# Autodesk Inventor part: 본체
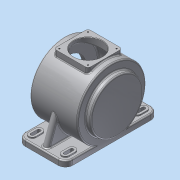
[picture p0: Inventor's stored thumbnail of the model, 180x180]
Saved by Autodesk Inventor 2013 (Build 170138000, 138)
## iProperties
Created: 2015-06
Part Number: 본체
Material: 알루미늄 6061
Document SubType Name: Modeling
Designer: Administrator
Density: 2.71 g/cm^3
Mass: 3326.36 g
Surface Area: 2312.89 cm^2
Volume: 1227.44 cm^3
Author: Administrator
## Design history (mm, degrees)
sketch "스케치1"
  geometry: L1 (-59, 115)-(59, 115); L2 (59, 115)-(59, -115); L3 (59, -115)-(-59, -115); L4 (-59, -115)-(-59, 115); L5 (-59, -115)-(59, 115); 2 further points
  constraints: 10 end point, 2 parallel, 1 coincident, 1 horizontal, 1 midpoint, 1 perpendicular
  dimensions: "d0" = 118 distance of L2.end L3.end; "d1" = 230 distance of L1.end L2.end
extrude "돌출1" new body sketch "스케치1" distance "d2" = 14; taper "d3" = 0 deg
sketch "스케치2"
  geometry: L1 (0, 0)-(0, 230) reference; L2 (0, 230)-(14, 230) reference; L3 (170, 202.523)-(170, -41.172); C1 r 85 at (85, 115); 2 further points
  constraints: 2 end point, 1 centre point, 1 horizontal alignment, 1 midpoint, 1 perpendicular
  dimensions: "d4" = 170 diameter of C1; "d6" = 85 distance from line of L3 C1.centre; "d59" = 85 distance from line of L1 C1.centre
extrude "돌출2" join sketch "스케치2" distance "d7" = 118; taper "d8" = 0 deg
sketch "스케치4"
  geometry: C1 r 65 at (-85, 115); A1 r 85 centre (-85, 115) between (-14, 161.733) and (-14, 68.267) reference; 1 further point
  constraints: 1 centre point, 1 coincident
  dimensions: "d12" = 130 diameter of C1
extrude "돌출4" join sketch "스케치4" distance "d13" = 13; taper "d14" = 0 deg
fillet "모깎기1" dims "d15" = 18
sketch "스케치5"
  geometry: C1 r 65 at (0, 0); A1 r 85 centre (0, 0) between (-71, -46.733) and (-71, 46.733) reference; 1 further point
  constraints: 1 centre point, 1 coincident
  dimensions: "d16" = 130 diameter of C1
extrude "돌출5" join sketch "스케치5" distance "d17" = 3; taper "d18" = 0 deg
node "작업 평면1"
sketch "스케치6"
  geometry: L1 (-35.5, -42.5)-(35.5, -42.5); L2 (42.5, -35.5)-(42.5, 35.5); L3 (35.5, 42.5)-(-35.5, 42.5); L4 (-42.5, 35.5)-(-42.5, -35.5); L5 (-42.5, -42.5)-(42.5, 42.5); A1 r 7 centre (-35.5, 35.5) between (-35.5, 42.5) and (-42.5, 35.5); A2 r 7 centre (35.5, 35.5) between (42.5, 35.5) and (35.5, 42.5); A3 r 7 centre (35.5, -35.5) between (35.5, -42.5) and (42.5, -35.5); A4 r 7 centre (-35.5, -35.5) between (-42.5, -35.5) and (-35.5, -42.5); 4 further points
  constraints: 10 end point, 8 point on circle, 8 point on line, 8 tangent, 4 centre point, 3 equal radius, 2 parallel, 1 coincident, 1 horizontal, 1 midpoint, 1 perpendicular
  dimensions: "d20" = 85 distance of point (-42.5, 42.5) L5.end; "d21" = 85 distance of L5.end point (42.5, -42.5); "d107" = 7 radius of A1
extrude "돌출6" join sketch "스케치6" stored distance "d22" = 3; taper "d23" = 0 deg
sketch "스케치7"
  geometry: L1 (-41, -115)-(41, -115) reference; L2 (59, -97)-(59, -46.733) reference; L3 (41, -72)-(41, -72); L4 (50, -81)-(50, -97); L5 (41, -106)-(41, -106); L6 (32, -97)-(32, -81); A1 r 9 centre (41, -97) between (41, -106) and (50, -97); A2 r 9 centre (41, -97) between (32, -97) and (41, -106); A3 r 9 centre (41, -81) between (41, -72) and (32, -81); A4 r 9 centre (41, -81) between (50, -81) and (41, -72); 4 further points
  constraints: 8 end point, 8 point on circle, 8 tangent, 6 point on line, 4 centre point, 3 equal radius, 2 parallel, 1 horizontal, 1 perpendicular
  dimensions: "d33" = 18 distance of point (50, -106) point (32, -106); "d34" = 34 distance of point (50, -72) point (50, -106); "d35" = 9 distance between parallel lines of L2 L4; "d36" = 9 distance between parallel lines of L1 L5; "d37" = 9 radius of A1
extrude "돌출7" join sketch "스케치7" distance "d31" = 3; taper "d32" = 0 deg
sketch "스케치8"
  geometry: L1 (-9, -16)-(-9, 0) reference; L2 (9, 0)-(9, -16) reference; L3 (-4, 4)-(4, 4); L4 (4, 4)-(4, -20); L5 (4, -20)-(-4, -20); L6 (-4, -20)-(-4, 4); A1 r 9 centre (0, 0) between (9, 0) and (-9, 0) reference; A2 r 9 centre (0, -16) between (-9, -16) and (9, -16) reference; A3 r 9 centre (0, 0) between (9, 0) and (-9, 0) reference; 1 further point
  constraints: 8 end point, 2 parallel, 1 horizontal, 1 perpendicular
  dimensions: "d41" = 5 distance between parallel lines of L1 L6; "d42" = 5 distance between parallel lines of L2 L4; "d43" = 4 distance from line of A1.centre L3; "d44" = 4 distance from line of A2.centre L5
extrude "돌출8" cut sketch "스케치8" stored distance "d45" = 3; taper "d46" = 0 deg
fillet "모깎기3" dims "d47" = 4
node "작업 평면5"
sketch "스케치9"
  geometry: L1 (71, -109)-(-9, -79.882); L2 (-9, -79.882)-(-9, 79.882); L3 (-9, 79.882)-(71, 109); L4 (71, 109)-(71, -109); L5 (85, -97)-(85, 97) reference; L6 (71, -46.733)-(71, -97) reference; L7 (85, -115)-(71, -115) reference; L8 (71, 115)-(85, 115) reference; L9 (71, -115)-(71, -97) reference; L10 (71, 97)-(71, 115) reference; 1 further point
  constraints: 8 end point, 1 collinear, 1 parallel, 1 vertical
  dimensions: "d49" = 6 distance from line of L7 L1.start; "d50" = 6 distance from line of L8 L3.end; "d51" = 110 deg angle of L9 L1; "d52" = 110 deg angle of L10 L3; "d53" = 80 distance between parallel lines of L2 L4
extrude "돌출9" join sketch "스케치9" stored distance "d54" = 15; taper "d55" = 0 deg
fillet "모깎기4" dims "d56" = 7.5
fillet "모깎기5" dims "d57" = 3
sketch "스케치10"
  geometry: L1 (-61.5, 85)-(62, 85); L2 (-41, 0)-(41, 0) reference; L3 (59, 150)-(62, 150) reference; L4 (59, 20)-(62, 20) reference; L5 (-61.5, 85)-(-61.5, 108.5); L6 (-61.5, 108.5)-(-47.5, 108.5); L7 (-47.5, 108.5)-(-47.5, 114.368); L8 (-47.5, 114.368)-(-51, 116); L9 (-51, 116)-(-51, 162); L10 (-51, 162)-(51, 162); L11 (51, 162)-(51, 132.5); L12 (51, 132.5)-(62, 132.5); L13 (62, 132.5)-(62, 85); L14 (62, 20)-(62, 150) reference; 1 further point
  constraints: 20 end point, 5 parallel, 3 perpendicular, 1 collinear, 1 horizontal
  dimensions: "d58" = 85 distance between parallel lines of L1 L2; "d60" = 115 deg angle of L9 L8; "d61" = 95 diameter of L12 L1; "d62" = 154 diameter of L10 L1; "d63" = 11 distance between parallel lines of L11 L13; "d64" = 102 distance of L9.end L10.end; "d66" = 47 diameter of L6 L1; "d67" = 14 distance of L5.end L6.end; "d68" = 3.5 distance between parallel lines of L9 L7; "d108" = 62 diameter of L8.end L1
revolve "회전1" sketch "스케치10" stored, may be unused: angle "d69" = 90 deg
sketch "스케치13"
  geometry: C1 r 23.5 at (0, 0) reference; C2 r 15 at (0, 0); 1 further point
  constraints: 1 centre point, 1 coincident
  dimensions: "d70" = 30 diameter of C2
extrude "돌출10" cut sketch "스케치13" distance "d71" = 3; taper "d72" = 0 deg
fillet "모깎기6" dims "d73" = 3
fillet "모깎기7" dims "d74" = 0.3
fillet "모깎기8" dims "d75" = 3
fillet "모깎기9" dims "d76" = 3
sketch "스케치14"
  geometry: C1 r 35 at (0, 0); 1 further point
  constraints: 1 centre point, 1 coincident
  dimensions: "d77" = 70 diameter of C1
extrude "돌출11" cut sketch "스케치14" stored distance "d78" = 3; taper "d79" = 0 deg
chamfer "모따기1" distance "d80" = 1; stored, may be unused: second distance "d81" = 2, angle "d82" = 45 deg
sketch "스케치15"
  geometry: C1 r 47.5 at (0, 0) reference; 2 further points
  constraints: 1 horizontal alignment
  dimensions: "d83" = 55 distance of C1.centre point (55, 0)
hole "구멍1" sketch "스케치15" at (55, 0) diameter "d84" = 3.242; stored, may be unused: countersink angle "d88" = 90 deg, drill point angle "d90" = 118 deg; dims "d85" = 10, "d86" = 4, "d87" = 2, "d89" = 13
sketch "스케치16"
  geometry: A1 r 7 centre (-35.5, -35.5) between (-42.5, -35.5) and (-35.5, -42.5) reference
hole "구멍2" sketch "스케치16" at (-35.5, -35.5) diameter "d94" = 3.242; stored, may be unused: countersink angle "d98" = 90 deg, drill point angle "d100" = 118 deg; dims "d95" = 10, "d96" = 4, "d97" = 2, "d99" = 13
fillet "모깎기10" dims "d101" = 3
fillet "모깎기11" dims "d102" = 3
fillet "모깎기12" dims "d103" = 3
fillet "모깎기13" dims "d104" = 3
fillet "모깎기14" dims "d105" = 3
node "솔리드1"
mirror "대칭1"
mirror "대칭2"
mirror "대칭3"
mirror "대칭4"
pattern_circular "원형 패턴1" dims angle "d92" = 360 deg
mirror "대칭5"
mirror "대칭6"
node "작업 평면2"
node "작업 평면3"
node "작업 평면4"
other parameters: "d19" = 173, "d48" = -72
